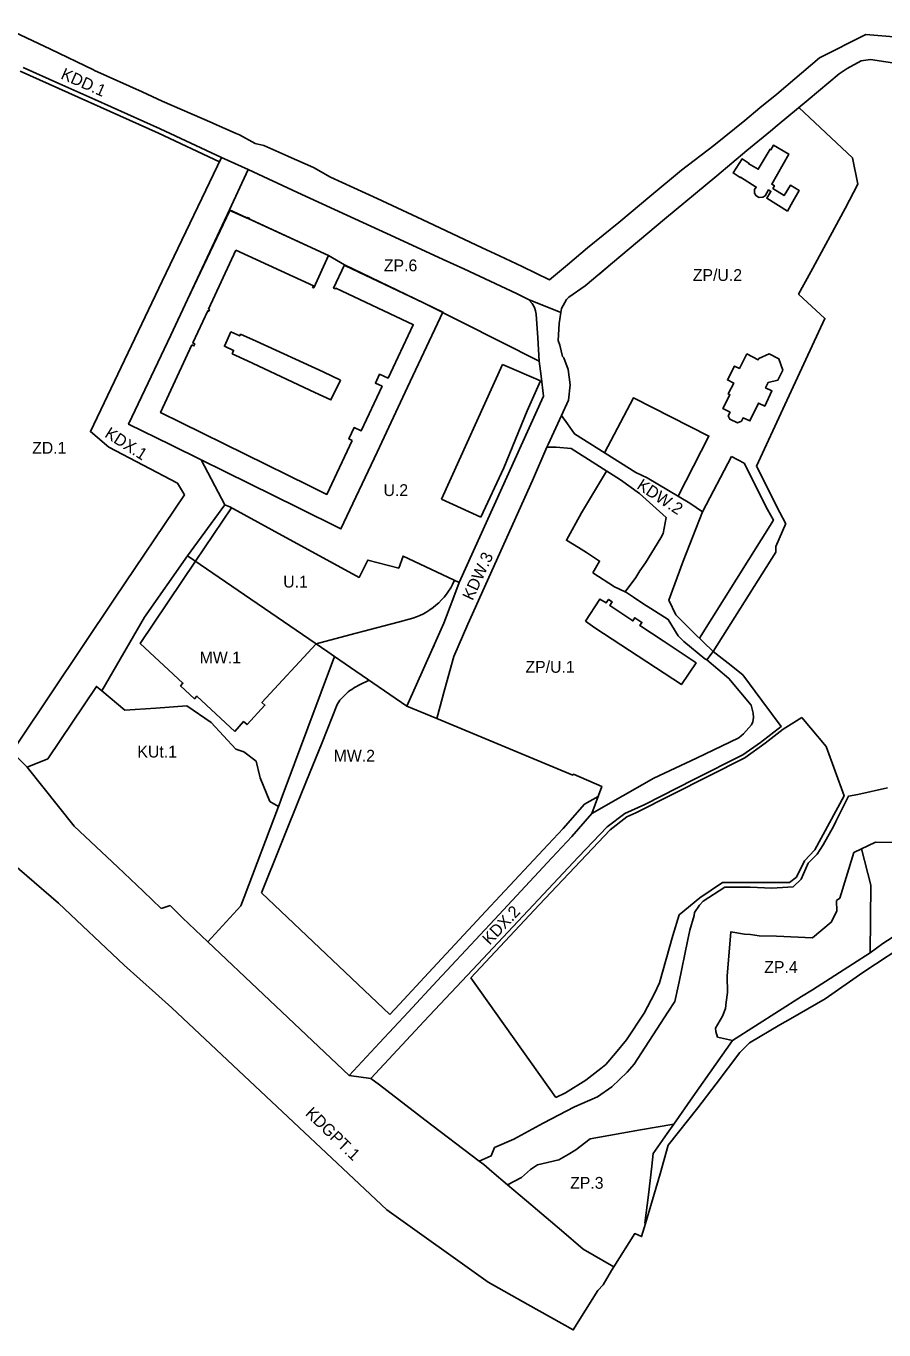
# Model space of a CAD drawing. Extents: x 7427219 to 7428976, y 5542673 to 5543767.
# Drawn here: x 7427663 to 7428025, y 5542673 to 5543224 of the extents above; entities that cross this region are included whole.
import ezdxf

# ---------------------------------------------------------------- set-up
doc = ezdxf.new("R2010")
doc.units = 0
for name, color, linetype in [('linie rozgraniczające', 7, 'Continuous'), ('nieprzekraczalna_linia_lokalizacyjna', 7, 'Continuous'), ('nieprzekraczalne linie zabudowy', 7, 'Continuous'), ('obowiazujace linie zabudowy', 7, 'Continuous'), ('przeznaczenia terenów', 7, 'Continuous')]:
    doc.layers.add(name, color=color, linetype=linetype)

msp = doc.modelspace()

# ---------------------------------------------------------------- linework, layer by layer
at = {"layer": 'linie rozgraniczające'}
for p, q in [((7427756.62, 5543163.15), (7427748.71, 5543146.16)), ((7427793.18, 5542957.47), (7427790.32, 5542959.43)), ((7427834.85, 5542961.5), (7427823.72, 5542936.57)), ((7427953.18, 5542959.62), (7427950.47, 5542956.05)), ((7427663.24, 5542910.82), (7427683.21, 5542885.89)), ((7427683.21, 5542885.89), (7427701.59, 5542868.5)), ((7427701.59, 5542868.5), (7427712.29, 5542858.37)), ((7427712.29, 5542858.37), (7427719.97, 5542851.1)), ((7427719.97, 5542851.1), (7427723.73, 5542852.35)), ((7427723.73, 5542852.35), (7427728.92, 5542847.2))]:
    msp.add_line(p, q, dxfattribs=at)
for points in [[(7428044.78, 5543217.92), (7428017.58, 5543220.26), (7427998.01, 5543210.28), (7427980.08, 5543195.04), (7427972.87, 5543189.19), (7427966.51, 5543183.92), (7427953.34, 5543173.39), (7427939.74, 5543162.86), (7427927.19, 5543152.53), (7427913.22, 5543140.83), (7427900.07, 5543130.07), (7427891.55, 5543122.94), (7427884.01, 5543116.63), (7427872.4, 5543122.17), (7427862.83, 5543126.73), (7427855.57, 5543130.13), (7427830.12, 5543142), (7427811.13, 5543151), (7427791.51, 5543159.91), (7427784.2, 5543164.08), (7427773.76, 5543168.69), (7427773.4, 5543168.85), (7427763.32, 5543173.27), (7427760.17, 5543174.09), (7427759.63, 5543174.23), (7427752.96, 5543177.84), (7427751.58, 5543178.45), (7427742.06, 5543182.66), (7427741.46, 5543182.91), (7427720.34, 5543191.98), (7427711.87, 5543195.95), (7427691.73, 5543205.04), (7427691.32, 5543205.24), (7427673.14, 5543214.07), (7427662.95, 5543218.86), (7427652.55, 5543223.76)], [(7427661.57, 5543206.3), (7427676.7, 5543199.54), (7427691.82, 5543192.78), (7427705.68, 5543186.58), (7427719.54, 5543180.39), (7427732.45, 5543174.31), (7427745.35, 5543168.23)], [(7427899.06, 5543114.07), (7427910.6, 5543123.72), (7427932.63, 5543142.15), (7427954.66, 5543160.57), (7427967.39, 5543171.15), (7427977.31, 5543179.36), (7427980.12, 5543181.72), (7427993.22, 5543192.62), (7428006.32, 5543203.52), (7428009.75, 5543205.87), (7428015.62, 5543209.07), (7428019.58, 5543209.69), (7428039.05, 5543206.75), (7428058.53, 5543203.82), (7428063.91, 5543203.12)], [(7427904.75, 5543118.83), (7427910.6, 5543123.72), (7427932.63, 5543142.15), (7427954.66, 5543160.57), (7427967.39, 5543171.15), (7427977.31, 5543179.36), (7427980.12, 5543181.72), (7427993.22, 5543192.62), (7428006.32, 5543203.52), (7428009.75, 5543205.87), (7428015.62, 5543209.07), (7428019.58, 5543209.69), (7428039.05, 5543206.75), (7428058.53, 5543203.82), (7428063.91, 5543203.12)], [(7427953.18, 5542959.62), (7427979.65, 5543001.62), (7427979.55, 5543003.92), (7427983.8, 5543013.72), (7427983.74, 5543013.8), (7427981.22, 5543018.33), (7427971.38, 5543037.89), (7427983.43, 5543063.75), (7428000.34, 5543100.29), (7427989.21, 5543110.51), (7427994.32, 5543119.91), (7428008.88, 5543146.69), (7428014.23, 5543156.99), (7428011.94, 5543168.06), (7427989.25, 5543189.31)], [(7427745.35, 5543168.23), (7427720.37, 5543116), (7427690.01, 5543052.52), (7427697.79, 5543045.88), (7427726.77, 5543030.74), (7427729.71, 5543025.77)], [(7427745.35, 5543168.23), (7427750.99, 5543165.69), (7427756.62, 5543163.15)], [(7427756.62, 5543163.15), (7427777.47, 5543153.54), (7427798.32, 5543143.94), (7427818.69, 5543134.55), (7427839.06, 5543125.16), (7427847.73, 5543121.17), (7427858.91, 5543116.01), (7427870.08, 5543110.86), (7427875.09, 5543108.27)], [(7427879.65, 5543082.27), (7427830.72, 5543106.84), (7427797.39, 5543122.95), (7427790.6, 5543126.89), (7427748.71, 5543146.16), (7427731.08, 5543108.28), (7427723.95, 5543093.23), (7427706.13, 5543055.6), (7427723.92, 5543046.84), (7427736.84, 5543040.51), (7427746.78, 5543021.62), (7427731.09, 5542999.98), (7427712.81, 5542974.1), (7427694.86, 5542942.98)], [(7427889.42, 5543084.27), (7427888.37, 5543088.94), (7427887.67, 5543090.94), (7427888.05, 5543098.13), (7427888.8, 5543102.85), (7427889.05, 5543104.45), (7427889.05, 5543104.45), (7427891.12, 5543108.32), (7427892.13, 5543109.32), (7427899.06, 5543114.07)], [(7427875.09, 5543108.27), (7427888.8, 5543102.85)], [(7427879.65, 5543082.27), (7427878.98, 5543092.16), (7427878.3, 5543102.04), (7427878.1, 5543103.53), (7427877.57, 5543104.89), (7427876.64, 5543106.53), (7427875.09, 5543108.27)], [(7427889.42, 5543084.27), (7427889.96, 5543083.68), (7427891.86, 5543078.66), (7427892.7, 5543072.25), (7427892, 5543065.81), (7427889.01, 5543059.29), (7427883.37, 5543047.01), (7427882.87, 5543045.87), (7427876.79, 5543031.85), (7427849.5, 5542971.16), (7427843.56, 5542957.46), (7427839.79, 5542943.82), (7427836.34, 5542931.32)], [(7427879.65, 5543082.27), (7427880.39, 5543075.97)], [(7427845.82, 5542988.7), (7427881.4, 5543067.47), (7427880.39, 5543075.97)], [(7427808.44, 5542779.34), (7427831.08, 5542803.48), (7427853.71, 5542827.62), (7427874.98, 5542850.28), (7427896.24, 5542872.94), (7427908.4, 5542885.55), (7427915.77, 5542891.25), (7427924.28, 5542895.05), (7427944.97, 5542905.52), (7427965.66, 5542915.99), (7427973.05, 5542921.15), (7427981.86, 5542927.98), (7427973.75, 5542938.9), (7427965.64, 5542949.82), (7427959.41, 5542954.72), (7427953.18, 5542959.62), (7427944.87, 5542967.59), (7427937.34, 5542975.09), (7427934.39, 5542981.27), (7427940.49, 5542997.71), (7427944.52, 5543008.12), (7427948.55, 5543018.54), (7427943.26, 5543022.2), (7427925.23, 5543032.98), (7427920.38, 5543035.27), (7427894.49, 5543051.54), (7427891.61, 5543055.81), (7427889.01, 5543059.29)], [(7427901.9, 5542891.14), (7427928.03, 5542906.11), (7427946.03, 5542914.62), (7427964.02, 5542923.13), (7427965.95, 5542924.81), (7427969.29, 5542928.6), (7427969.85, 5542929.9), (7427970.17, 5542931.74), (7427970, 5542933.6), (7427969.2, 5542936.95), (7427959.79, 5542948.24), (7427950.47, 5542956.05), (7427949.65, 5542956.57), (7427940.71, 5542963.83), (7427938.31, 5542966.18), (7427934.12, 5542973.2), (7427926.75, 5542977.73), (7427923.76, 5542979.66), (7427919.46, 5542982.5), (7427916.48, 5542984.55), (7427915.92, 5542984.79), (7427920.38, 5542990.9), (7427922.15, 5542993.72), (7427924.49, 5542997.08), (7427930.98, 5543007.69), (7427931.99, 5543009.5), (7427933.24, 5543016.19), (7427921.94, 5543026.4), (7427913.97, 5543032.06), (7427893.08, 5543045.34), (7427886.75, 5543045.92), (7427882.87, 5543045.87)], [(7427729.71, 5543025.77), (7427700.38, 5542982.08), (7427659.59, 5542921.33), (7427656.8, 5542917.2)], [(7427746.78, 5543021.62), (7427748.85, 5543020.66), (7427766.63, 5543010.99), (7427803.55, 5542990.89), (7427807.26, 5542998.21), (7427820.25, 5542994.84), (7427822.11, 5542999.94), (7427845.82, 5542988.7)], [(7427790.32, 5542959.43), (7427731.09, 5542999.98)], [(7427843.12, 5542981.58), (7427845.82, 5542988.7)], [(7427835.25, 5542962.11), (7427834.85, 5542961.5), (7427839.32, 5542971.53), (7427843.12, 5542981.58)], [(7427769.41, 5542894.21), (7427770.25, 5542896.05), (7427770.55, 5542897.24), (7427793.18, 5542957.47), (7427799.88, 5542952.88)], [(7427823.72, 5542936.57), (7427799.88, 5542952.88)], [(7427740.98, 5542929.63), (7427730.79, 5542936.73), (7427717.7, 5542935.75), (7427704.6, 5542934.78), (7427694.86, 5542942.98), (7427692.58, 5542944.89), (7427671.96, 5542914.23), (7427663.24, 5542910.82)], [(7427901.9, 5542891.14), (7427906.05, 5542902.66), (7427894.13, 5542907.83), (7427893.8, 5542907.42), (7427836.34, 5542931.32), (7427823.72, 5542936.57)], [(7427769.41, 5542894.21), (7427765.78, 5542896.29), (7427761.77, 5542906.3), (7427761.55, 5542906.84), (7427760.05, 5542913.25), (7427754.9, 5542917.24), (7427751.45, 5542918.33), (7427740.98, 5542929.63)], [(7427656.8, 5542917.2), (7427663.24, 5542910.82)], [(7427854.28, 5542744.36), (7427859.38, 5542746.59), (7427860.75, 5542750.07), (7427868.84, 5542753.7), (7427881.28, 5542760.39), (7427894.57, 5542767.34), (7427904.25, 5542771.55), (7427910.35, 5542775.77), (7427916.8, 5542781.93), (7427919.78, 5542785.35), (7427933.98, 5542807.26), (7427936.86, 5542811.81), (7427938.82, 5542820.09), (7427942.3, 5542837.23), (7427943.31, 5542841.9), (7427945.09, 5542848.18), (7427945.27, 5542849.41), (7427947.3, 5542852.42), (7427948.94, 5542854.23), (7427958.1, 5542860.11), (7427968.69, 5542860.12), (7427977.91, 5542859.72), (7427986.89, 5542860.21), (7427990.3, 5542863.49), (7427993.26, 5542870.2), (7427997.07, 5542874.06), (7427999.58, 5542878), (7428004.04, 5542885.98), (7428004.89, 5542887.86), (7428010.36, 5542898.55), (7428014.31, 5542899.28), (7428026.79, 5542902.07)], [(7427739.64, 5542837.06), (7427753.62, 5542852.2), (7427754.98, 5542855.8), (7427769.41, 5542894.21)], [(7427799.35, 5542780.61), (7427812.17, 5542794.35), (7427824.25, 5542807.31), (7427836.57, 5542820.48), (7427860.78, 5542846.49), (7427884.99, 5542872.49), (7427893.4, 5542881.52), (7427901.9, 5542891.14)], [(7427649.66, 5542876.48), (7427676.46, 5542853.3), (7427704.28, 5542827.17), (7427717.55, 5542815.38), (7427724.44, 5542809.19), (7427752.63, 5542782.65), (7427815.21, 5542723.74), (7427858, 5542693.29), (7427874.82, 5542683.86), (7427894.04, 5542673.09), (7427904.33, 5542689.78), (7427906.69, 5542692.08), (7427910.19, 5542698.17), (7427911.19, 5542699.75)], [(7427961.35, 5542795.36), (7427954.97, 5542796.75), (7427954.25, 5542799.07), (7427954.14, 5542800.6), (7427957, 5542805.58), (7427958.29, 5542808.86), (7427958.57, 5542811.54), (7427959.16, 5542815.64), (7427958.98, 5542822.55), (7427960.52, 5542841.17), (7427966.41, 5542840.21), (7427968.94, 5542840.09), (7427972.57, 5542839.49), (7427979.9, 5542839.39), (7427995.1, 5542838.69), (7428003.03, 5542845.25), (7428005.41, 5542849.93), (7428005.29, 5542854.45), (7428006.57, 5542855.44), (7428012.57, 5542874.7), (7428021.7, 5542879.15), (7428032.91, 5542878.92)], [(7428019.51, 5542832.35), (7428019.77, 5542860.88), (7428015.86, 5542876.3)], [(7428048.48, 5542851.59), (7428041.66, 5542847.1), (7428024.83, 5542836.36)], [(7427728.92, 5542847.2), (7427739.64, 5542837.06), (7427763.17, 5542814.81), (7427799.35, 5542780.61)], [(7427924.47, 5542718.04), (7427930.66, 5542739.04), (7427934.16, 5542751.15), (7427946.59, 5542766.83), (7427954.44, 5542777), (7427964.36, 5542790.19), (7427968.41, 5542794.33), (7427981.32, 5542801.92), (7427985.74, 5542804.52), (7428000.42, 5542812.87), (7428016.3, 5542823.99), (7428037.38, 5542837.79), (7428037.77, 5542836.88), (7428052.28, 5542847.66)], [(7428019.51, 5542832.35), (7428004.52, 5542822.81)], [(7428024.83, 5542836.36), (7428019.51, 5542832.35)], [(7428004.52, 5542822.81), (7427995.05, 5542816.79)], [(7427936.52, 5542760.05), (7427944.55, 5542771.48), (7427961.35, 5542795.36), (7427990.43, 5542813.86), (7427995.05, 5542816.79)], [(7427799.35, 5542780.61), (7427808.44, 5542779.34)], [(7427808.44, 5542779.34), (7427812.08, 5542776.57), (7427831.36, 5542761.85), (7427854.28, 5542744.36)], [(7427866.27, 5542734.36), (7427872.11, 5542737.45), (7427875.95, 5542740.84), (7427878.88, 5542742.77), (7427887.87, 5542744.88), (7427891.93, 5542747.21), (7427895.13, 5542749.09), (7427901.17, 5542753.86), (7427922.4, 5542757.58), (7427936.52, 5542760.05)], [(7427936.52, 5542760.05), (7427933.65, 5542755.98), (7427927.75, 5542747.59), (7427927.22, 5542742.21), (7427925.75, 5542730.21), (7427924.27, 5542718.21), (7427924.47, 5542718.04)], [(7427854.28, 5542744.36), (7427856.19, 5542742.91), (7427859.59, 5542740.03), (7427866.27, 5542734.36)], [(7427866.27, 5542734.36), (7427874.29, 5542727.55), (7427888.99, 5542715.07), (7427898.25, 5542707.21), (7427911.19, 5542699.75)], [(7427911.19, 5542699.75), (7427920.01, 5542713.76), (7427922.85, 5542712.52), (7427924.47, 5542718.04)]]:
    msp.add_lwpolyline(points, dxfattribs=at)
at = {"layer": 'nieprzekraczalna_linia_lokalizacyjna'}
for points in [[(7427990.6, 5542931.78), (7427982.7, 5542926.88), (7427975.06, 5542920.86), (7427966.47, 5542914.73), (7427920.49, 5542891.51), (7427916.59, 5542889.85), (7427909.54, 5542884.3), (7427879.63, 5542852.58), (7427850.74, 5542821.8)], [(7427886.67, 5542771.21), (7427890.73, 5542773.16), (7427899.29, 5542778.56), (7427905.62, 5542783.55), (7427907.71, 5542785.19), (7427911.88, 5542790.01), (7427916.53, 5542795.62), (7427924.04, 5542806.8), (7427928.29, 5542815.11), (7427930.47, 5542819.64), (7427936.09, 5542839.74), (7427938.82, 5542848.44), (7427947.54, 5542855.58), (7427957.07, 5542862), (7427985.37, 5542862.03), (7427988.3, 5542864.31), (7427991.65, 5542871.25), (7427996.11, 5542875.81), (7428008.41, 5542898.67), (7428000.8, 5542919.52), (7427990.6, 5542931.78)], [(7427850.74, 5542821.8), (7427886.67, 5542771.21)]]:
    msp.add_lwpolyline(points, dxfattribs=at)
at = {"layer": 'nieprzekraczalne linie zabudowy'}
for p, q in [((7427864.12, 5543080.8), (7427838.34, 5543023.91)), ((7427880.11, 5543073.98), (7427864.12, 5543080.8)), ((7427966.18, 5543039.15), (7427960.81, 5543041.96)), ((7427736.84, 5543040.51), (7427777.67, 5543020.37)), ((7427749.58, 5543020.26), (7427734.41, 5542997.71)), ((7427838.35, 5543023.92), (7427855.03, 5543016.37)), ((7427816.76, 5542971.15), (7427820.62, 5542972.17)), ((7427820.62, 5542972.17), (7427824.63, 5542973.22)), ((7427779.19, 5542899.74), (7427762.28, 5542857.63))]:
    msp.add_line(p, q, dxfattribs=at)
for points in [[(7427744.49, 5543166.43), (7427718.71, 5543178.57), (7427660.31, 5543204.67)], [(7427756.26, 5543142.59), (7427748.92, 5543145.94), (7427731.08, 5543108.28)], [(7427790.6, 5543126.89), (7427756.93, 5543142.28), (7427757.09, 5543142.65), (7427756.43, 5543142.96), (7427756.26, 5543142.59)], [(7427811.11, 5543043.81), (7427824, 5543071.19), (7427838.95, 5543102.95), (7427830.72, 5543106.84), (7427797.75, 5543122.44), (7427797.88, 5543122.71), (7427797.39, 5543122.95)], [(7427723.95, 5543093.23), (7427706.13, 5543055.6), (7427723.92, 5543046.84), (7427736.84, 5543040.51)], [(7427855.03, 5543016.37), (7427864.67, 5543037.18), (7427874.47, 5543061.27), (7427880.11, 5543073.98)], [(7427777.67, 5543020.37), (7427795.86, 5543011.41), (7427811.11, 5543043.81), (7427824, 5543071.19)], [(7427938.3, 5543025.16), (7427951.3, 5543050.63), (7427919.44, 5543066.75), (7427907.28, 5543043.5)], [(7427960.81, 5543041.96), (7427948.55, 5543018.54)], [(7427908.09, 5543035.8), (7427897.55, 5543018.13), (7427891.09, 5543006.61), (7427896.17, 5543003.49), (7427899.55, 5543001.48), (7427905.12, 5542997.83), (7427902.32, 5542992.89)], [(7427947.33, 5542965.23), (7427978.56, 5543015.02), (7427976.02, 5543019.59), (7427966.18, 5543039.15)], [(7427902.32, 5542992.89), (7427911.5, 5542986.95), (7427915.92, 5542984.79)], [(7427785.35, 5542962.83), (7427799.58, 5542966.63), (7427816.76, 5542971.15), (7427820.62, 5542972.17)], [(7427807.75, 5542947.5), (7427803.72, 5542945.51), (7427803.45, 5542945.38), (7427802.67, 5542944.97), (7427801.89, 5542944.53), (7427801.13, 5542944.07), (7427800.39, 5542943.59), (7427799.65, 5542943.09), (7427798.95, 5542942.55), (7427795.34, 5542939.01), (7427794.33, 5542937.28)], [(7427794.33, 5542937.28), (7427787.87, 5542921.22), (7427782.6, 5542908.12), (7427779.19, 5542899.74)], [(7427816.51, 5542806.36), (7427820.6, 5542810.72), (7427832.91, 5542823.89), (7427857.12, 5542849.89), (7427881.33, 5542875.9), (7427889.7, 5542884.88), (7427898.7, 5542895.07), (7427904.52, 5542898.4)], [(7427762.28, 5542857.63), (7427784.12, 5542836.97), (7427816.51, 5542806.36)]]:
    msp.add_lwpolyline(points, dxfattribs=at)
msp.add_arc((7427817.25, 5543001.27), 29, 284.7401, 335.9136, dxfattribs=at)
at = {"layer": 'obowiazujace linie zabudowy'}
for p, q in [((7427739.89, 5543104.21), (7427751.39, 5543129.09)), ((7427782.27, 5543029.72), (7427728.52, 5543056.18))]:
    msp.add_line(p, q, dxfattribs=at)
for points in [[(7427984.59, 5543145.63), (7427986.79, 5543149.62), (7427989.41, 5543154.38), (7427985.78, 5543156.54), (7427983.1, 5543152.19), (7427978.39, 5543155.19), (7427979.01, 5543156.3), (7427977.88, 5543156.94), (7427985.04, 5543169.68), (7427978.6, 5543173.44), (7427977.5, 5543171.56), (7427977.14, 5543171.77), (7427972.2, 5543163.29), (7427968.18, 5543165.52), (7427968.27, 5543165.79), (7427965.36, 5543167.67), (7427961.53, 5543161.74), (7427964.57, 5543159.77), (7427964.72, 5543160), (7427971.31, 5543155.74), (7427970.63, 5543154.67), (7427970.63, 5543153.24), (7427971.33, 5543152.09), (7427972.6, 5543151.37), (7427974.11, 5543151.48), (7427975.1, 5543152.12), (7427976.57, 5543154.53), (7427977.51, 5543153.96), (7427975.73, 5543151.04)], [(7427967.37, 5543085.36), (7427964.21, 5543079.18), (7427962.07, 5543080.14), (7427959.13, 5543074.3), (7427961.79, 5543072.97), (7427959.47, 5543068.42), (7427960.19, 5543068.05), (7427957.22, 5543062.23), (7427960.28, 5543060.67), (7427959.46, 5543059.08), (7427960.13, 5543057.74), (7427963.43, 5543056.25), (7427965.03, 5543056.87), (7427965.78, 5543058.27), (7427968.67, 5543056.97), (7427972.22, 5543064.52), (7427974.91, 5543063.25), (7427977.94, 5543069.7), (7427975.26, 5543070.95), (7427976.32, 5543073.2), (7427980.49, 5543074.23), (7427982.54, 5543078.47), (7427980.88, 5543083.28), (7427976.84, 5543085.39), (7427972.46, 5543083.34), (7427972.18, 5543082.87)], [(7427899.12, 5542972.46), (7427903.17, 5542969.6), (7427939.74, 5542945.65), (7427945.88, 5542954.81), (7427932.03, 5542964.08), (7427922.2, 5542970.53), (7427923.03, 5542971.87), (7427919.99, 5542973.84), (7427919.2, 5542972.51), (7427909.43, 5542979.05), (7427910.49, 5542980.58), (7427908.97, 5542981.58), (7427907.87, 5542980.11), (7427905.29, 5542981.72)]]:
    msp.add_lwpolyline(points, close=True, dxfattribs=at)
for points in [[(7427751.39, 5543129.09), (7427784.22, 5543114.09), (7427783.9, 5543113.4), (7427784.34, 5543113.19), (7427790.6, 5543126.89)], [(7427797.39, 5543122.95), (7427792.74, 5543113.1), (7427793.52, 5543112.73), (7427793.67, 5543113.06), (7427826.49, 5543097.54), (7427826.37, 5543097.6), (7427815.76, 5543075.06), (7427812.2, 5543076.74), (7427810.42, 5543072.97), (7427813.23, 5543071.65), (7427804.35, 5543052.79), (7427801.43, 5543054.16), (7427799.2, 5543049.42), (7427800.67, 5543048.73)], [(7427732.89, 5543089.1), (7427733.73, 5543088.71), (7427734.12, 5543089.55), (7427733.28, 5543089.93), (7427739.58, 5543103.55), (7427739.99, 5543103.35), (7427740.31, 5543104.01), (7427739.89, 5543104.21)], [(7427795.65, 5543074.18), (7427788.4, 5543077.7), (7427760.04, 5543090.63), (7427753.43, 5543093.62), (7427753.1, 5543092.89), (7427749.39, 5543094.57), (7427746.66, 5543088.54), (7427750.53, 5543086.79), (7427749.87, 5543085.34)], [(7427728.52, 5543056.18), (7427719.68, 5543060.53), (7427732.89, 5543089.1)], [(7427749.87, 5543085.34), (7427756.34, 5543082.41), (7427784.88, 5543068.99), (7427791.62, 5543065.86), (7427795.65, 5543074.18)], [(7427800.67, 5543048.73), (7427789.94, 5543025.94), (7427782.27, 5543029.72)], [(7427734.41, 5542997.71), (7427711.06, 5542963.01), (7427729.09, 5542946.27), (7427728.08, 5542945.18), (7427733.99, 5542939.69), (7427735, 5542940.77), (7427751.07, 5542925.85)], [(7427751.07, 5542925.85), (7427754.69, 5542930.04), (7427756.19, 5542928.75), (7427763.72, 5542936.89), (7427762.46, 5542938.06), (7427785.35, 5542962.83)]]:
    msp.add_lwpolyline(points, dxfattribs=at)

# ---------------------------------------------------------------- texts
at = {"layer": 'przeznaczenia terenów'}
for s, rotation, p in [('KDD.1', 336.2512, (7427677.12, 5543201.71)), ('KDX.1', 327.6289, (7427695.66, 5543050.47)), ('KDW.2', 326.8685, (7427920.49, 5543028.67)), ('KDW.3', 65.184, (7427851.47, 5542980.84)), ('KDX.2', 46.5318, (7427858.7, 5542835.35)), ('KDGPT.1', 315.8889, (7427780.46, 5542764.11))]:
    msp.add_text(s, height=5, rotation=rotation, dxfattribs=at).set_placement(p)
for s, p in [('ZP.6', (7427813.99, 5543120.18)), ('ZP/U.2', (7427944.52, 5543116.11)), ('ZD.1', (7427665.38, 5543043.13)), ('U.2', (7427813.83, 5543025.27)), ('U.1', (7427771.47, 5542986.61)), ('MW.1', (7427736.16, 5542954.59)), ('ZP/U.1', (7427873.81, 5542950.63)), ('KUt.1', (7427709.85, 5542914.84)), ('MW.2', (7427792.78, 5542913.11)), ('ZP.4', (7427974.71, 5542823.86)), ('ZP.3', (7427892.69, 5542732.7))]:
    msp.add_text(s, height=5, dxfattribs=at).set_placement(p)

doc.saveas('drawing.dxf')
